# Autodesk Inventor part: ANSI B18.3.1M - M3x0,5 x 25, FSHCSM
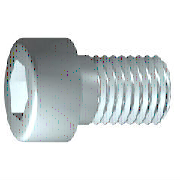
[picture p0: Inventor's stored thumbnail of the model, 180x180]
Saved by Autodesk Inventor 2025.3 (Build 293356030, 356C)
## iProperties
Created: 2024-01
Part Number: ANSI B18.3.1M - M3x0,5 x 25, FSHCSM
Material: Acciaio, Dolce
Description: Vite forgiata a testa incassata - Metrico
Document SubType Name: Modeling
Standard: ANSI B18.3.1M
Designer: R5800u
Standard Revision: 1979
Standards Organization: ANSI
Language: it-IT
Size Designation: M3x0,5 x 25
Categories: <MemberInstance><Categories><Category DisplayName="Elementi di fissaggio" InternalName="e4da775c-781d-43d5-af7c-5136215cf5a6" Mnemonic="FSTN"><Category DisplayN
Density: 7.85 g/cm^3
Appearance: Semilucidato
IsCustomPart: 0
Author: R5800u
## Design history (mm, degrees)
body "Solid1"
workplane "Work Plane1"
fillet "Fillet2" dims "d30" = 0.1 (= R)
revolve "Corpo" stored, may be unused: angle "d10" = 90 deg
sketch "Schizzo2"
  geometry: L1 (0, -3.85)-(0, 3.85) reference; L2 (-3.85, 0)-(3.85, 0) reference; L3 (1.443, 0)-(0.722, -1.25); L4 (0.722, -1.25)-(-0.722, -1.25); L5 (-0.722, -1.25)-(-1.443, 0); L6 (-1.443, 0)-(-0.722, 1.25); L7 (-0.722, 1.25)-(0.722, 1.25); L8 (0.722, 1.25)-(1.443, 0); 2 further points
  constraints: 12 end point, 1 coincident, 1 horizontal alignment, 1 point on line, 12 other
extrude "Intaglio" join sketch "Schizzo2" stored distance "d11" = 10; taper "d12" = 0 deg
fillet "Raccordo1" dims "d17" = 0.3 (= RR)
feature "Filettatura" dims "d13" = 18 (= GEL), "d14" = 0
chamfer "Smusso1" distance "d15" = 0.30673 (= -0.5 x SPD + 0.5 x GD); stored, may be unused: second distance "d16" = 0.30673 (= GUL), angle "d27" = 45 deg
sketch "Schizzo1"
  geometry: L1 (-0.667, 0)-(25, 0); L2 (25, 0)-(25, 1.5); L3 (25, 1.5)-(7, 1.5); L4 (7, 1.5)-(6.693, 1.5); L5 (6.693, 1.5)-(0, 1.5); L6 (0, 1.5)-(0, 2.75); L7 (0, 2.75)-(-3, 2.75); L8 (-3, 2.75)-(-3, 1.443); L9 (-3, 1.443)-(-1.5, 1.443); L10 (-1.5, 1.443)-(-0.667, 0); L11 (-8.6, 0)-(30.6, 0) reference; L12 (0, -0.55)-(0, 3.3) reference; L13 (7, 1.5)-(0, 1.5)
  constraints: 22 end point, 6 parallel, 2 collinear, 2 perpendicular, 1 horizontal, 1 point on line
  dimensions: "d1" = 18 distance from line of L3.end L2 (= GEL); "d2" = 0.30683 distance of L4.end L3.end (computed from GAL); "d3" = 3 distance between parallel lines of L8 L6 (= KOH); "d4" = 1.5 distance of L8.end L9.end (= INTI); "d5" = 60 deg angle of L10 L1; "d6" = 3 diameter of L3 L1 (= GD); "d7" = 3 diameter of L5 L1 (= BDM); "d8" = 2.88675 diameter of L9 L1 (= 1.1547 x SW); "d9" = 5.5 diameter of L7 L1 (= KOD); "d26" = 25 distance between parallel lines of L12 L2 (= NLG)
other parameters: "GD" = 3 (= NND) [user parameter; used in 2 equation terms], "NLG" = 25 [user parameter; used in 1 equation term], "GEL" = 18 [user parameter; used in 2 equation terms], "KOD" = 5.5 [user parameter; used in 1 equation term], "KOH" = 3 [user parameter; used in 1 equation term], "INTI" = 1.5 [user parameter; used in 1 equation term], "GAL" = 0.30673 (= 0.61345 x PTC) [user parameter; used in 1 equation term], "GUL" = 0.30673 (= 0.61345 x PTC) [user parameter; used in 1 equation term], "BDM" = 3 (= NND) [user parameter; used in 1 equation term], "SW" = 2.5 [user parameter; used in 2 equation terms], "RR" = 0.3 [user parameter; used in 1 equation term], "SPD" = 2.38655 [user parameter; used in 1 equation term], "d19" = 0, "d28" = 0, "d29" = 0, "R" = 0.1 [user parameter; used in 1 equation term], "TOA" = 30 deg [user parameter], "THREADDIA" = 3 [user parameter; used in 1 equation term], "PTC" = 0.5 [user parameter; used in 4 equation terms], "NND" = 3 [user parameter; used in 2 equation terms], "E0" = 2.8875 (= 1.155 x SW) [user parameter], "GD1" = 2.38655 (= THREADDIA - 1.2269 x PTC) [user parameter]
